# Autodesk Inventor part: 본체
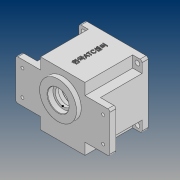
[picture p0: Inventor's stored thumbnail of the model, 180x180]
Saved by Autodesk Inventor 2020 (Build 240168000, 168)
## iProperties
Created: 2020-07
Part Number: 본체
Material: 일반
Document SubType Name: Modeling
Designer: PC312-
Density: 1 g/cm^3
Appearance: 기본값
Author: PC312-
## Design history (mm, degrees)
sketch "스케치1"
  geometry: L1 (33, -47)-(-33, -47); L2 (-33, -47)-(-33, 47); L3 (-33, 47)-(33, 47); L4 (33, 47)-(33, -47); L5 (33, -47)-(-33, 47); L6 (-33, -47)-(33, 47); L7 (70, 30)-(-70, 30); L8 (-70, 30)-(-70, -30); L9 (-70, -30)-(70, -30); L10 (70, -30)-(70, 30); L11 (70, 30)-(-70, -30); L12 (-70, 30)-(70, -30); 5 further points
  constraints: 24 end point, 4 midpoint, 4 parallel, 2 horizontal, 2 perpendicular
  dimensions: "d0" = 66 distance of L2.end L3.end; "d1" = 94 distance of L1.end L2.end; "d2" = 140 distance of L9.end L8.end; "d3" = 60 distance of L8.end L7.end
extrude "돌출2" new body sketch "스케치1" distance "d6" = 71; taper "d7" = 0 deg
extrude "돌출3" join sketch "스케치1" distance "d8" = 80; taper "d9" = 0 deg
sketch "스케치3"
  geometry: C1 r 27.5 at (0, 11); 1 further point
  constraints: 1 centre point, 1 vertical alignment
  dimensions: "d13" = 55 diameter of C1; "d14" = 11 distance of point (0, 0) C1.centre
extrude "돌출4" join sketch "스케치3" distance "d15" = 7; taper "d16" = 0 deg
sketch "스케치4"
  geometry: C1 r 27.5 at (0, 0) reference; C2 r 16 at (0, 0); 1 further point
  constraints: 1 centre point, 1 coincident
  dimensions: "d17" = 32 diameter of C2
extrude "돌출5" cut sketch "스케치4" distance "d18" = 8.3; taper "d19" = 0 deg
sketch "스케치5"
  geometry: C1 r 27.5 at (0, 0) reference; C2 r 12.5 at (0, 0); 1 further point
  constraints: 1 centre point, 1 coincident
  dimensions: "d20" = 25 diameter of C2
extrude "돌출6" cut sketch "스케치5" distance "d21" = 9; taper "d22" = 0 deg
node "작업 평면3"
sketch "스케치7"
  geometry: L1 (-47, -47)-(47, -47); L2 (47, -47)-(47, 47); L3 (47, 47)-(-47, 47); L4 (-47, 47)-(-47, -47); L5 (-47, -47)-(47, 47); L6 (47, -47)-(-47, 47); 1 further point
  constraints: 12 end point, 2 midpoint, 2 parallel, 1 horizontal, 1 perpendicular
  dimensions: "d27" = 94 distance of L3.end L2.end; "d28" = 94 distance of L2.end L1.end
extrude "돌출7" join sketch "스케치7" distance "d29" = 9; taper "d30" = 0 deg
sketch "스케치9"
  geometry: C1 r 43 at (0, 0); 1 further point
  constraints: 1 centre point, 1 coincident
  dimensions: "d32" = 86 diameter of C1
extrude "돌출8" cut sketch "스케치9" distance "d33" = 9; taper "d34" = 0 deg
sketch "스케치10"
  geometry: C1 r 40 at (0, 0); 1 further point
  constraints: 1 centre point, 1 coincident
  dimensions: "d35" = 80 diameter of C1
extrude "돌출9" cut sketch "스케치10" distance "d36" = 62; taper "d37" = 0 deg
sketch "스케치14"
  geometry: L1 (80, 80)-(-14, 80) reference; L2 (66, 0)-(0, 0) reference; 3 further points
  constraints: 1 midpoint, 1 vertical alignment, 1 other
  dimensions: "d54" = 40 distance from line of L1 point (33, 40)
feature "엠보싱1" sketch "스케치14" dims "d55" = 1, "d56" = 0
sketch "스케치15"
  geometry: C1 r 40 at (0, 0) reference; C2 r 43 at (0, 0) reference; A1 r 36 centre (0, 0) between (35.778, 3.994) and (35.778, -3.994); A2 r 4 centre (36, 0) between (35.778, 3.994) and (35.778, -3.994); A3 r 4 centre (-36, 0) between (-35.778, -3.994) and (-35.778, 3.994); 1 further point
  constraints: 9 point on circle, 3 centre point, 2 horizontal alignment, 1 coincident, 1 tangent
  dimensions: "d57" = 72 diameter of A1; "d58" = 8 diameter of A2; "d59" = 8 diameter of A3
sketch "스케치17"
  geometry: A1 r 21 centre (0, 11) between (8.978, -7.984) and (-8.978, -7.984); A2 r 15 centre (0, -20) between (-8.978, -7.984) and (8.978, -7.984); 1 further point
  constraints: 4 point on circle, 3 vertical alignment, 2 centre point
  dimensions: "d60" = 42 diameter of A1; "d61" = 11 distance of point (0, 0) A1.centre; "d62" = 30 diameter of A2; "d63" = 20 distance of A2.centre point (0, 0)
extrude "돌출15" join sketch "스케치17" distance "d64" = 7; taper "d65" = 0 deg
sketch "스케치18"
  geometry: C1 r 11 at (0, -20); 1 further point
  constraints: 1 centre point, 1 vertical alignment
  dimensions: "d66" = 22 diameter of C1; "d67" = 20 distance of C1.centre point (0, 0)
extrude "돌출16" cut sketch "스케치18" distance "d68" = 7; taper "d69" = 0 deg
sketch "스케치19"
  geometry: C1 r 11 at (0, 0) reference; C2 r 9.5 at (0, 0); 1 further point
  constraints: 1 centre point, 1 coincident
  dimensions: "d70" = 19 diameter of C2
extrude "돌출17" cut sketch "스케치19" distance "d71" = 3; taper "d72" = 0 deg
sketch "스케치20"
  geometry: C1 r 17.5 at (0, 11); A1 r 21 centre (0, 11) between (8.978, -7.984) and (-8.978, -7.984) reference; 1 further point
  constraints: 1 centre point, 1 coincident
  dimensions: "d73" = 35 diameter of C1
extrude "돌출18" cut sketch "스케치20" distance "d74" = 10; taper "d75" = 0 deg
fillet "모깎기1" dims "d76" = 3
chamfer "모따기1" distance "d77" = 1; stored, may be unused: second distance "d78" = 2, angle "d79" = 45 deg
chamfer "모따기2" distance "d80" = 1; stored, may be unused: second distance "d81" = 2, angle "d82" = 45 deg
chamfer "모따기3" distance "d83" = 1; stored, may be unused: second distance "d84" = 2, angle "d85" = 45 deg
chamfer "모따기4" distance "d86" = 0.8; stored, may be unused: second distance "d87" = 2, angle "d88" = 30 deg
fillet "모깎기2" dims "d89" = 3
sketch "스케치21"
  geometry: 1 further point
sketch "스케치22"
  geometry: 1 further point
sketch "스케치23"
  geometry: L1 (47, 30)-(47, 44) reference; L2 (44, 47)-(33, 47) reference; 2 further points
  dimensions: "d90" = 7 distance from line of L1 point (40, 40); "d91" = 7 distance from line of point (40, 40) L2
hole "구멍1" sketch "스케치23" at (40, 40) diameter "d92" = 7; stored, may be unused: countersink angle "d96" = 90 deg, drill point angle "d98" = 118 deg; dims "d93" = 6, "d94" = 4, "d95" = 2, "d97" = 8
sketch "스케치24"
  geometry: L1 (-44, -47)-(-33, -47) reference; L2 (-47, -30)-(-47, -44) reference; 2 further points
  dimensions: "d105" = 7 distance from line of L1 point (-40, -40); "d106" = 7 distance from line of L2 point (-40, -40)
hole "구멍2" sketch "스케치24" at (-40, -40) diameter "d107" = 7; stored, may be unused: countersink angle "d111" = 90 deg, drill point angle "d113" = 118 deg; dims "d108" = 6, "d109" = 4, "d110" = 2, "d112" = 8
sketch "스케치26"
  geometry: L1 (-23, 71)-(-23, 80) reference; L2 (-23, 71)-(-23, 0); L3 (0, 0)-(-37, 0) reference; L4 (-23, 71)-(0, 71) reference; L5 (-23, 71)-(0, 71); L6 (0, 0)-(0, 71) reference; L7 (0, 71)-(0, 0); L8 (0, 0)-(-23, 0); 1 further point
  constraints: 8 end point, 2 horizontal, 2 vertical, 1 point on line
extrude "돌출19" cut sketch "스케치26" extent not by distance; stored distance "d115" = 14; taper "d116" = 0 deg
sketch "스케치27"
  geometry: L1 (0, 0)-(37, 0) reference; L2 (23, 71)-(23, 0); L3 (23, 0)-(0, 0); L4 (23, 71)-(0, 71) reference; L5 (0, 71)-(23, 71); L6 (0, 0)-(0, 71) reference; L7 (0, 0)-(0, 71); 1 further point
  constraints: 8 end point, 2 horizontal, 2 vertical, 1 point on line
extrude "돌출20" cut sketch "스케치27" extent not by distance; stored distance "d117" = 0; taper "d118" = 0 deg
sketch "스케치28"
  geometry: L1 (33, 30)-(47, 30) reference; L2 (33, 30)-(70, 30); L3 (70, 30)-(70, -30); L4 (33, -47)-(33, -30) reference; L5 (33, -30)-(70, -30); L6 (47, -30)-(47, 30) reference; 2 further points
  constraints: 6 end point, 2 horizontal, 1 vertical
  dimensions: "d119" = 23 distance between parallel lines of L3 L6
extrude "돌출21" join sketch "스케치28" distance "d120" = 9; taper "d121" = 0 deg
fillet "모깎기3" dims "d122" = 3
sketch "스케치30"
  geometry: L1 (-70, 27)-(-70, -27) reference; L2 (-47, 30)-(-67, 30) reference; 2 further points
  dimensions: "d123" = 10 distance from line of L1 point (-60, 19); "d124" = 11 distance from line of point (-60, 19) L2
hole "구멍3" sketch "스케치30" at (-60, 19) diameter "d125" = 4.5; stored, may be unused: countersink angle "d129" = 90 deg, drill point angle "d131" = 0 deg; dims "d126" = 6, "d127" = 10, "d128" = 5, "d130" = 13
sketch "스케치32"
  geometry: C1 r 2 at (36, 0); C2 r 40 at (0, 0) reference; C3 r 2 at (-36, 0); A1 r 36 centre (0, 0) between (36, 0) and (-36, 0); A2 r 4 centre (36, 0) between (35.778, 3.994) and (35.778, -3.994); A3 r 4 centre (-36, 0) between (-35.778, -3.994) and (-35.778, 3.994); 3 further points
  constraints: 10 point on circle, 5 centre point, 3 coincident, 2 horizontal alignment
  dimensions: "d149" = 72 diameter of A1; "d150" = 8 diameter of A2; "d151" = 4 diameter of C1; "d152" = 8 diameter of A3; "d153" = 4 diameter of C3
extrude "돌출23" join sketch "스케치32" distance "d156" = 79; taper "d157" = 0 deg
node "솔리드2"
pattern_linear "직사각형 패턴1" dims "d101" = 80
pattern_linear "직사각형 패턴2" dims "d104" = 80
mirror "미러1"
pattern_linear "직사각형 패턴3" dims "d134" = 120
pattern_linear "직사각형 패턴5" dims "d140" = 38
feature "A9D066F2-1C7D-4E18-AEED-F7BC21143FA4" dims "d92" = 7, "d93" = 6, "d94" = 4, "d95" = 2, "d96" = 90 deg, "d97" = 8, "d98" = 118 deg
